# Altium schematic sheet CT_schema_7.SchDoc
size 274 x 160 mm
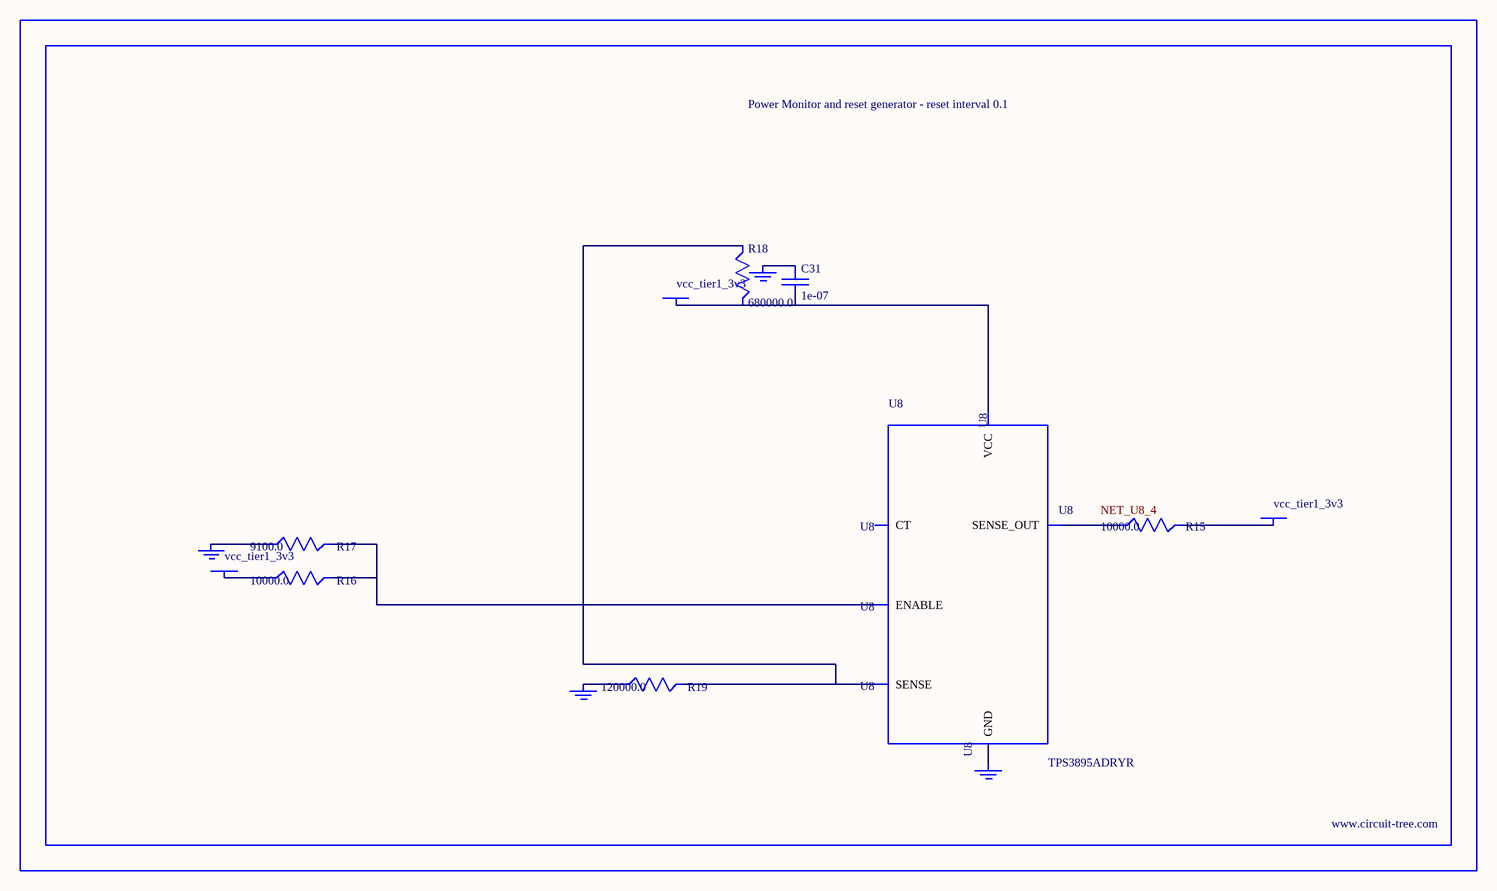
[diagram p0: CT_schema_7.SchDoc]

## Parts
BORDER6  (no value)
C31  1e-07  [C0402]
GND_INSTANCE_6_0  (no value)
GND_INSTANCE_6_1  (no value)
GND_INSTANCE_6_2  (no value)
GND_INSTANCE_6_3  (no value)
POWER_INSTANCE_6_0  vcc_tier1_3v3
POWER_INSTANCE_6_1  vcc_tier1_3v3
POWER_INSTANCE_6_2  vcc_tier1_3v3
R15  10000.0  [R0603]
R16  10000.0  [R0603]
R17  9100.0  [R0603]
R18  680000.0  [R0603]
R19  120000.0  [R0603]
U8  TPS3895ADRYR  [SON-6]

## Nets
NetC31_1: C31.1 GND_INSTANCE_6_2.0(GND)
NetC31_2: C31.2 POWER_INSTANCE_6_2.0(PWR) R18.2 U8.6(VCC)
NetGND_INSTANCE_6_0_0: GND_INSTANCE_6_0.0(GND) R17.1
NetGND_INSTANCE_6_1_0: GND_INSTANCE_6_1.0(GND) R19.1
NetGND_INSTANCE_6_3_0: GND_INSTANCE_6_3.0(GND) U8.2(GND)
NetPOWER_INSTANCE_6_0_0: POWER_INSTANCE_6_0.0(PWR) R16.1
NetPOWER_INSTANCE_6_1_0: POWER_INSTANCE_6_1.0(PWR) R15.2
NetR15_1: R15.1 U8.4(SENSE_OUT)
NetR16_2: R16.2 R17.2 U8.1(ENABLE)
NetR18_1: R18.1 R19.2 U8.3(SENSE)

Not connected (* = marked no-connect by the designer): U8 5(CT)

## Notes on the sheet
- Labels drawn without touching a wire or pin: NET_U8_4

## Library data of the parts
BORDER6 = BORDER_PAGE6
C31 = C0402C104K3RACTU
GND_INSTANCE_6_0-GND_INSTANCE_6_3 = GND
POWER_INSTANCE_6_0-POWER_INSTANCE_6_2 = PWR
R15 R16 = RC0603JR-0710KL
R17 = RC0603JR-079K1L
R18 = RC0603JR-07680KL
R19 = RC0603JR-07120KL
